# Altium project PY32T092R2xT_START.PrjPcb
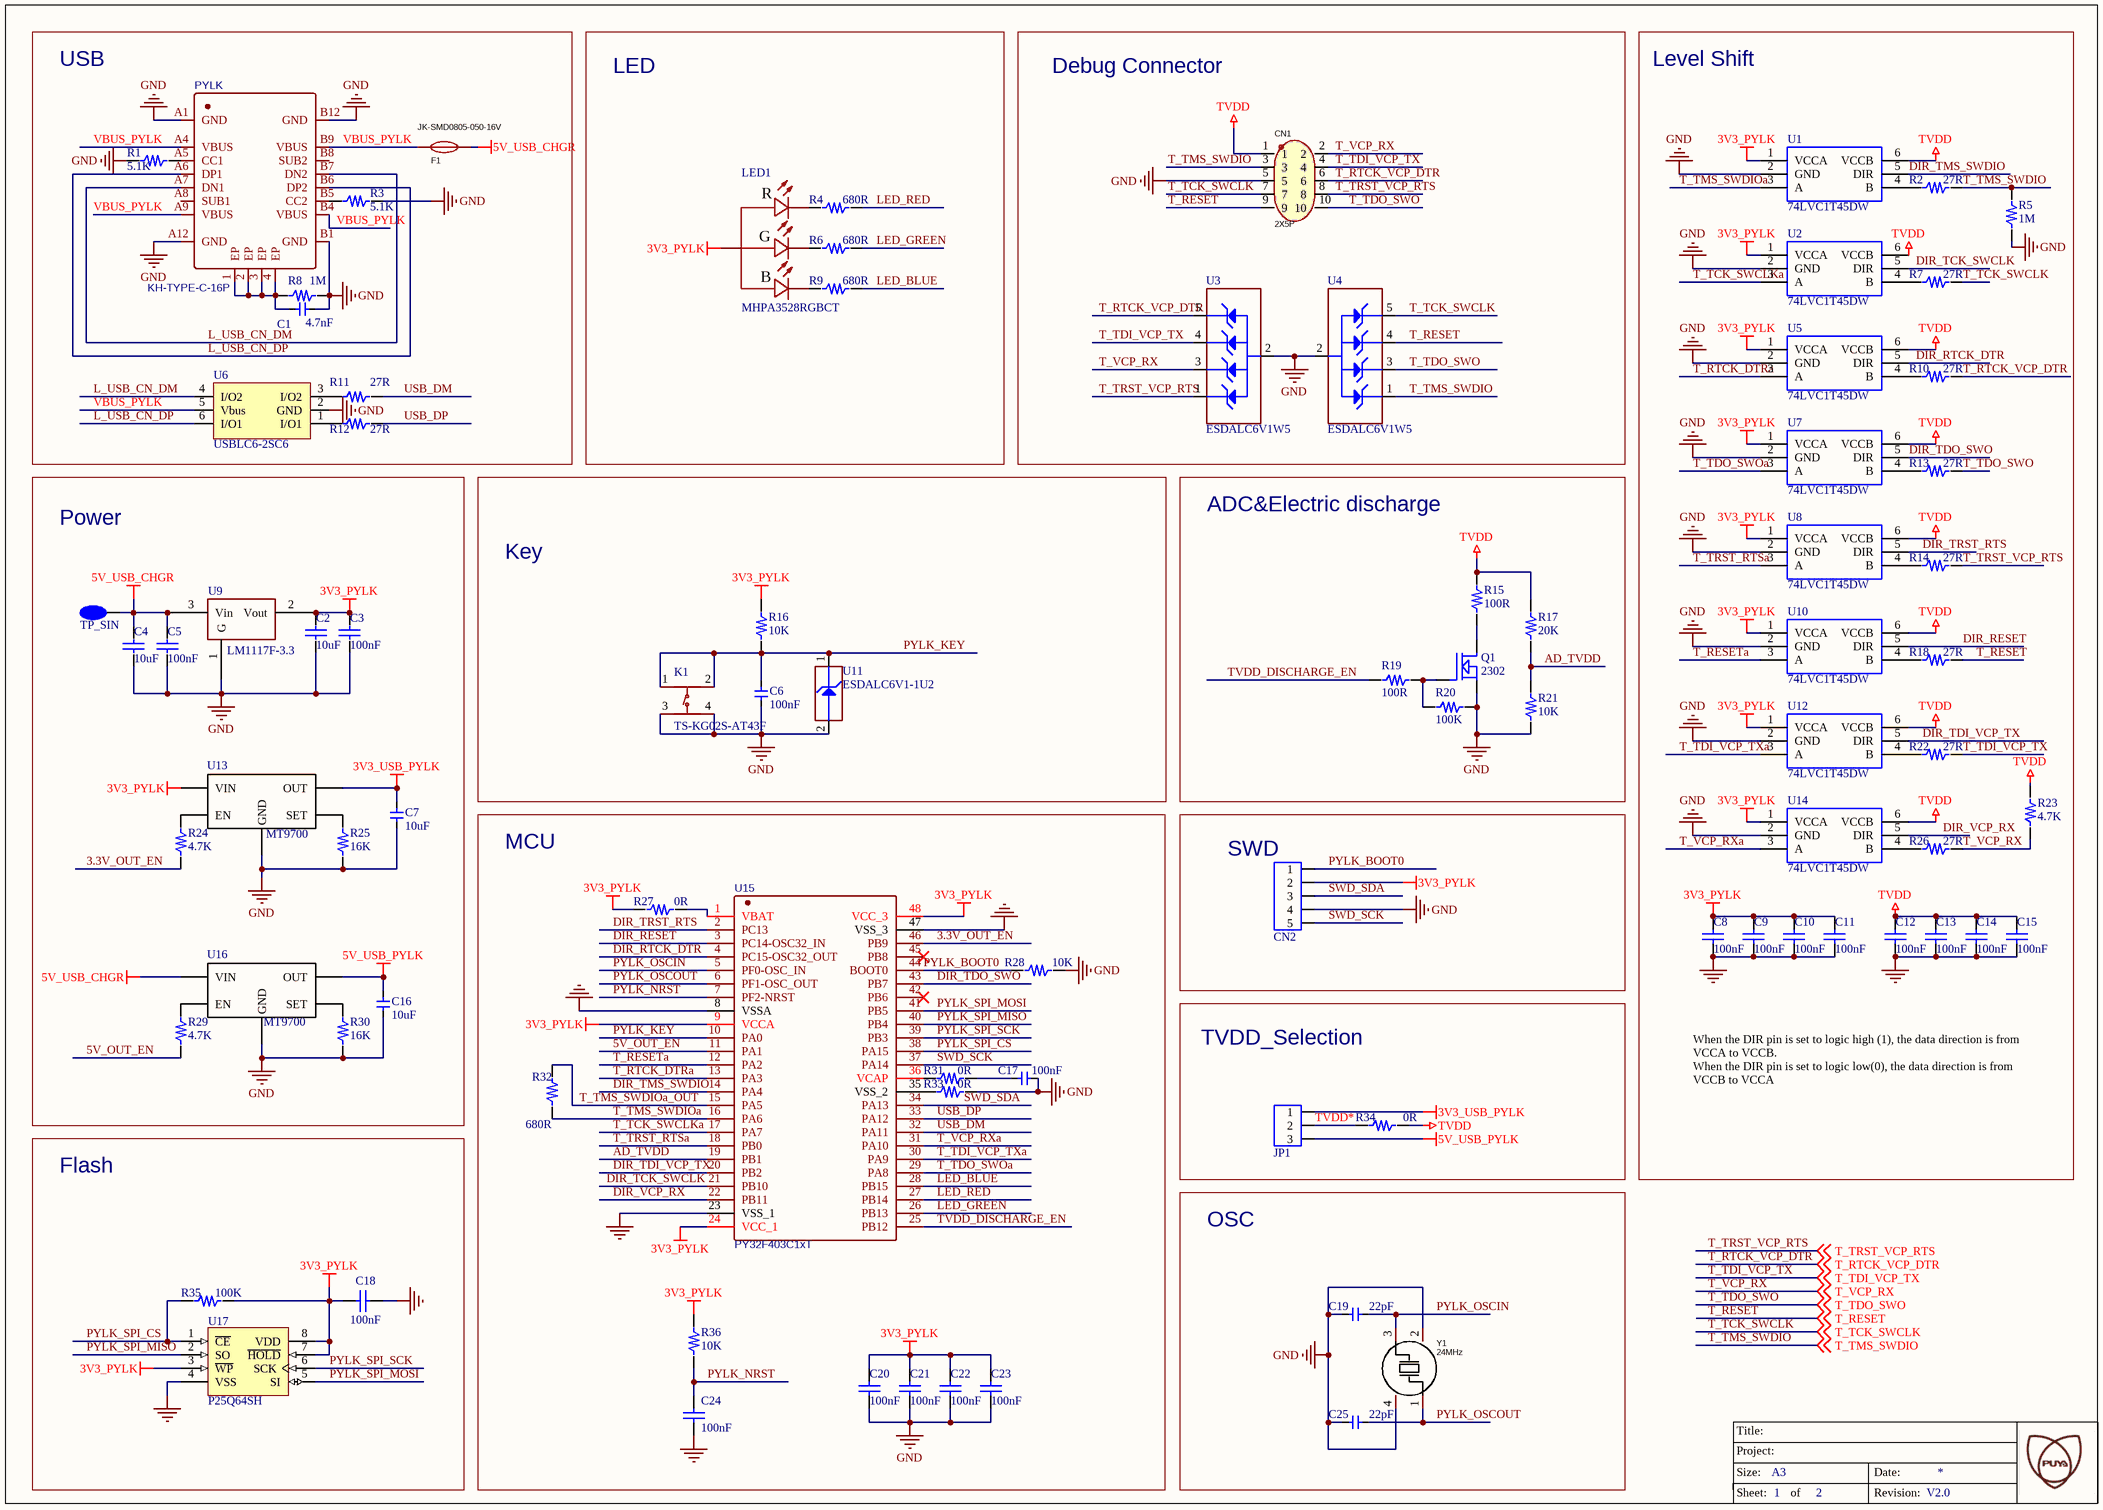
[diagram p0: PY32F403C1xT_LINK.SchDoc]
2 sheets, 144 parts. Net scope: global (net labels, ports and power ports of the same name join across sheets).
Board file: PY32T092R2xT_START.PcbDoc
Sheets:
  PY32F403C1xT_LINK.SchDoc
  PY32T092R2xT_START.SchDoc

## Sheet PY32F403C1xT_LINK.SchDoc: =DocumentName
size A3; Revision: V2.0; SheetNumber: 1; SheetTotal: 2; Project: PY32T092R2xT_START.PrjPcb

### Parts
5V_USB_CHGR  TP_SIN  [TP_SIN]
C1  4.7nF  [C0603]
C2  10uF  [C0805]
C3  100nF  [C0603]
C4  10uF  [C0805]
C5  100nF  [C0603]
C6  100nF  [C0603]
C7  10uF  [C0805]
C8  100nF  [C0603]
C9  100nF  [C0603]
C10  100nF  [C0603]
C11  100nF  [C0603]
C12  100nF  [C0603]
C13  100nF  [C0603]
C14  100nF  [C0603]
C15  100nF  [C0603]
C16  10uF  [C0805]
C17  100nF  [C0603]
C18  100nF  [C0603]
C19  22pF  [C0603]
C20  100nF  [C0603]
C21  100nF  [C0603]
C22  100nF  [C0603]
C23  100nF  [C0603]
C24  100nF  [C0603]
C25  22pF  [C0603]
CN1  2X5P  [HDR2X5]
CN2  CON5  [CON5]  (value not drawn)
F1  JK-SMD0805-050-16V  [F0805]
JP1  CON3  [CON3]  (value not drawn)
K1  TS-KG02S-AT43F  [SW-SMD_4P-L6.0-W6.0-P4.50-LS8.5]
LED1  MHPA3528RGBCT  [LED-ARRAY-SMD_4P-L3.5-W2.8-TL]
PYLK  KH-TYPE-C-16P  [USB-C-SMD_KH-TYPE-C-16P]
Q1  2302  [SOT23]
R1  5.1K  [R0603]
R2  27R  [R0603]
R3  5.1K  [R0603]
R4  680R  [R0603]
R5  1M  [R0603]
R6  680R  [R0603]
R7  27R  [R0603]
R8  1M  [R0603]
R9  680R  [R0603]
R10  27R  [R0603]
R11  27R  [R0603]
R12  27R  [R0603]
R13  27R  [R0603]
R14  27R  [R0603]
R15  100R  [R0805]
R16  10K  [R0603]
R17  20K  [R0603]
R18  27R  [R0603]
R19  100R  [R0603]
R20  100K  [R0603]
R21  10K  [R0603]
R22  27R  [R0603]
R23  4.7K  [R0603]
R24  4.7K  [R0603]
R25  16K  [R0603]
R26  27R  [R0603]
R27  0R  [JP2_SMD]
R28  10K  [R0603]
R29  4.7K  [R0603]
R30  16K  [R0603]
R31  0R  [JP2_SMD]
R32  680R  [R0603]
R33  0R  [JP2_SMD]
R34  0R  [JP2_SMD]
R35  100K  [R0603]
R36  10K  [R0603]
U1  74LVC1T45DW  [SOT363]
U2  74LVC1T45DW  [SOT363]
U3  ESDALC6V1W5  [ESD_SOT323-5L]
U4  ESDALC6V1W5  [ESD_SOT323-5L]
U5  74LVC1T45DW  [SOT363]
U6  USBLC6-2SC6  [SOT23-6]
U7  74LVC1T45DW  [SOT363]
U8  74LVC1T45DW  [SOT363]
U9  LM1117F-3.3  [SOT-89-3_L4.5-W2.5-P1.50-LS4.2-BR]
U10  74LVC1T45DW  [SOT363]
U11  ESDALC6V1-1U2  [ESD_ST0201]
U12  74LVC1T45DW  [SOT363]
U13  MT9700  [SOT23-5]
U14  74LVC1T45DW  [SOT363]
U15  PY32F403C1xT  [LQFP-48_L7.0-W7.0-P0.50-LS9.0-BL]
U16  MT9700  [SOT23-5]
U17  P25Q64SH  [SOP-8P]
Y1  24MHz  [CRYSTAL-SMD_4P-L3.2-W2.5-BL]

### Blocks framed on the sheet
USB: C1 F1 PYLK R1 R3 R8 R11 R12 U6
LED: LED1 R4 R6 R9
Debug Connector: CN1 U3 U4
Level Shift: C8-C15 R2 R5 R7 R10 R13 R14 R18 R22 R23 R26 U1 U2 U5 U7 U8 U10 U12 U14
Power: 5V_USB_CHGR C2-C5 C7 C16 R24 R25 R29 R30 U9 U13 U16
Key: C6 K1 R16 U11
ADC&Electric discharge: Q1 R15 R17 R19-R21
MCU: C17 C20-C24 R27 R28 R31-R33 R36 U15
SWD: CN2
TVDD_Selection: JP1 R34
Flash: C18 R35 U17
OSC: C19 C25 Y1

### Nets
3V3_PYLK: C2.2 C3.2 C8.2 C9.2 C10.2 C11.2 C18.2 C20.2 C21.2 C22.2 C23.2 CN2.2 LED1.1(-) R16.2 R27.1 R35.2 R36.2 U1.1(VCCA) U2.1(VCCA) U5.1(VCCA) U7.1(VCCA) U8.1(VCCA) U9.2(Vout) U10.1(VCCA) U12.1(VCCA) U13.5(VIN) U14.1(VCCA) U15.9(VCCA) U15.24(VCC_1) U15.48(VCC_3) U17.3(~{WP}) U17.7(~{HOLD}) U17.8(VDD)
3V3_USB_PYLK: C7.2 JP1.1 U13.1(OUT)
5V_USB_CHGR: 5V_USB_CHGR.1(TP_SIN) C4.2 C5.2 F1.2 U9.3(Vin) U16.5(VIN)
5V_USB_PYLK: C16.2 JP1.3 U16.1(OUT)
GND: C1.1 C2.1 C3.1 C4.1 C5.1 C6.1 C7.1 C8.1 C9.1 C10.1 C11.1 C12.1 C13.1 C14.1 C15.1 C16.1 C17.1 C18.1 C19.1 C20.1 C21.1 C22.1 C23.1 C24.1 C25.1 CN1.5 CN2.4 K1.3 K1.4 PYLK.A1(GND) PYLK.A12(GND) PYLK.B1(GND) PYLK.B12(GND) Q1.2(S) R1.1 R3.2 R5.1 R8.2 R20.1 R21.1 R25.1 R28.2 R30.1 R33.2 U1.2(GND) U2.2(GND) U3.2(GND) U4.2(GND) U5.2(GND) U6.2(GND) U7.2(GND) U8.2(GND) U9.1(G) U10.2(GND) U11.2(GND) U12.2(GND) U13.2(GND) U14.2(GND) U15.8(VSSA) U15.23(VSS_1) U15.47(VSS_3) U16.2(GND) U17.4(VSS) Y1.2(GND) Y1.4(GND)
TVDD: C12.2 C13.2 C14.2 C15.2 CN1.1 R15.2 R17.2 R23.2 R34.2 U1.6(VCCB) U2.6(VCCB) U5.6(VCCB) U7.6(VCCB) U8.6(VCCB) U10.6(VCCB) U12.6(VCCB) U14.6(VCCB)
3.3V_OUT_EN: R24.1 U15.46(PB9)
5V_OUT_EN: R29.1 U15.11(PA1)
AD_TVDD: R17.1 R21.2 U15.19(PB1)
DIR_RESET: U10.5(DIR) U15.3(PC14-OSC32_IN)
DIR_RTCK_DTR: U5.5(DIR) U15.4(PC15-OSC32_OUT)
DIR_TCK_SWCLK: U2.5(DIR) U15.21(PB10)
DIR_TDI_VCP_TX: U12.5(DIR) U15.20(PB2)
DIR_TDO_SWO: U7.5(DIR) U15.43(PB7)
DIR_TMS_SWDIO: U1.5(DIR) U15.14(PA4)
DIR_TRST_RTS: U8.5(DIR) U15.2(PC13)
DIR_VCP_RX: U14.5(DIR) U15.22(PB11)
L_USB_CN_DM: PYLK.A7(DN1) PYLK.B7(DN2) U6.4(I/O2)
L_USB_CN_DP: PYLK.A6(DP1) PYLK.B6(DP2) U6.6(I/O1)
LED_BLUE: R9.2 U15.28(PB15)
LED_GREEN: R6.2 U15.26(PB13)
LED_RED: R4.2 U15.27(PB14)
PYLK_BOOT0: CN2.1 R28.1 U15.44(BOOT0)
PYLK_KEY: C6.2 K1.1 K1.2 R16.1 U11.1(IO1) U15.10(PA0)
PYLK_NRST: C24.2 R36.1 U15.7(PF2-NRST)
PYLK_OSCIN: C19.2 U15.5(PF0-OSC_IN) Y1.3(OSC2)
PYLK_OSCOUT: C25.2 U15.6(PF1-OSC_OUT) Y1.1(OSC1)
PYLK_SPI_CS: R35.1 U15.38(PA15) U17.1(~{CE})
PYLK_SPI_MISO: U15.40(PB4) U17.2(SO)
PYLK_SPI_MOSI: U15.41(PB5) U17.5(SI)
PYLK_SPI_SCK: U15.39(PB3) U17.6(SCK)
SWD_SCK: CN2.5 U15.37(PA14)
SWD_SDA: CN2.3 U15.34(PA13)
T_RESET: CN1.9 R18.2 U4.4(IO3) ; off-sheet T_RESET
T_RESETa: U10.3(A) U15.12(PA2)
T_RTCK_DTRa: U5.3(A) U15.13(PA3)
T_RTCK_VCP_DTR: CN1.6 R10.2 U3.5(IO4) ; off-sheet T_RTCK_VCP_DTR
T_TCK_SWCLK: CN1.7 R7.2 U4.5(IO4) ; off-sheet T_TCK_SWCLK
T_TCK_SWCLKa: U2.3(A) U15.17(PA7)
T_TDI_VCP_TX: CN1.4 R22.2 U3.4(IO3) ; off-sheet T_TDI_VCP_TX
T_TDI_VCP_TXa: U12.3(A) U15.30(PA9)
T_TDO_SWO: CN1.10 R13.2 U4.3(IO2) ; off-sheet T_TDO_SWO
T_TDO_SWOa: U7.3(A) U15.29(PA8)
T_TMS_SWDIO: CN1.3 R2.2 R5.2 U4.1(IO1) ; off-sheet T_TMS_SWDIO
T_TMS_SWDIOa: R32.1 U1.3(A) U15.16(PA6)
T_TMS_SWDIOa_OUT: R32.2 U15.15(PA5)
T_TRST_RTSa: U8.3(A) U15.18(PB0)
T_TRST_VCP_RTS: CN1.8 R14.2 U3.1(IO1) ; off-sheet T_TRST_VCP_RTS
T_VCP_RX: CN1.2 R23.1 R26.2 U3.3(IO2) ; off-sheet T_VCP_RX
T_VCP_RXa: U14.3(A) U15.31(PA10)
TVDD*: JP1.2 R34.1
TVDD_DISCHARGE_EN: R19.2 U15.25(PB12)
USB_DM: R11.2 U15.32(PA11)
USB_DP: R12.2 U15.33(PA12)
VBUS_PYLK: F1.1 PYLK.A4(VBUS) PYLK.A9(VBUS) PYLK.B4(VBUS) PYLK.B9(VBUS) U6.5(Vbus)
NetC1_2: C1.2 PYLK.1(EP) PYLK.2(EP) PYLK.3(EP) PYLK.4(EP) R8.1
NetC17_2: C17.2 R31.2
NetLED1_2: LED1.2(-) R9.1
NetLED1_3: LED1.3(-) R6.1
NetLED1_4: LED1.4(-) R4.1
NetPYLK_A5: PYLK.A5(CC1) R1.2
NetPYLK_B5: PYLK.B5(CC2) R3.1
NetQ1_1: Q1.1(G) R19.1 R20.2
NetQ1_3: Q1.3(D) R15.1
NetR2_1: R2.1 U1.4(B)
NetR7_1: R7.1 U2.4(B)
NetR10_1: R10.1 U5.4(B)
NetR11_1: R11.1 U6.3(I/O2)
NetR12_1: R12.1 U6.1(I/O1)
NetR13_1: R13.1 U7.4(B)
NetR14_1: R14.1 U8.4(B)
NetR18_1: R18.1 U10.4(B)
NetR22_1: R22.1 U12.4(B)
NetR24_2: R24.2 U13.4(EN)
NetR25_2: R25.2 U13.3(SET)
NetR26_1: R26.1 U14.4(B)
NetR27_2: R27.2 U15.1(VBAT)
NetR29_2: R29.2 U16.4(EN)
NetR30_2: R30.2 U16.3(SET)
NetR31_1: R31.1 U15.36(VCAP)
NetR33_1: R33.1 U15.35(VSS_2)

Not connected (* = marked no-connect by the designer): PYLK A8(SUB1) B8(SUB2); U15 42(PB6)* 45(PB8)*

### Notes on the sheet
- When the DIR pin is set to logic high (1), the data direction is from VCCA to VCCB.
  When the DIR pin is set to logic low(0), the data direction is from VCCB to VCCA

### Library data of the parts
C1 C3 C5 C6 C17 C19 C25 = C0603: PCB DECAL: 0603
C2 C4 C7 C16 = C0805: PCB DECAL: 0805
C8-C15 C18 C20-C24 = 贴片高压陶瓷电容: Capacitor (Semiconductor SIM Model); 器件封装(外观): 0603; Value: 104
CN1 = 2X5P: Manufacturer: XFCN(兴飞); Symbol: PZ254V-12-10P; Add into BOM: yes; Pitch: 2.54mm; Circluar Pins/Square Pins: 方针
F1 = JK-SMD0805-050-16V: Manufacturer: JK(金科); Add into BOM: yes; Voltage - Max: 6V; Current - Max: 100A; Hold Current: 500mA; Trip Current: 1A; Power Dissipation: 600mW; Resistance - Initial (Ri) (Min): 150mΩ; Resistance - Post Trip (R1) (Max): 850mΩ; Time to Trip(Max): 100ms
K1 = TS-KG02S-AT43F: Manufacturer: HANBO(汉博); Add into BOM: yes; Circuit: 单刀单掷; Actuator Style: 圆形按钮; Operating Force: 250gf; Switch Length: 6mm; Switch Height: 4.3mm; Strike Gundam: 不带; Contact Current: 50mA; Voltage Rating (DC): 12V; Insulation Resistance: 100MΩ; Actuator/Cap Color: 黑色; Pin Style: 鸥翼型
LED1 = MHPA3528RGBCT: Manufacturer: MEIHUA(美华); Add into BOM: yes
PYLK = KH-TYPE-C-16P: BOM_Manufacturer: Shenzhen Kinghelm Elec; Contributor: LCSC
Q1 = MOSFET N: Value: SI2302
R1-R14 R16-R24 R26-R29 R31-R36 = R0603: PCB DECAL: 0603
R15 = R0805: PCB DECAL: 0805
R25 R30 = R0603_7: 0603WAF1602T5E 16KΩ(1602) ±1%; PCB DECAL: 0603
U3 U4 = ESDALC6V1W5: Dual Transil array for ESD protection; Internal_Part_Number: MCD-00136; Part_Type: Diode; Manufacturer: STMICROELECTRONICS; ECCN_US: EAR99; ECCN_EU: NEC; Provided_By: Subcon; Initial_Board_Reference: MB1262
U6 = USBLC6-2SC6: Function: ESD EMI fliter
U11 = ESDALC6V1-1U2: ESD protection 6V1; Internal_Part_Number: MCD-00170; Part_Type: Diode; Manufacturer: STMICROELECTRONICS; ECCN_US: EAR99; ECCN_EU: NEC; Provided_By: Subcon; Initial_Board_Reference: MB1274
U15 = PY32F403C1xT: LQFP48; BOM_Manufacturer: PUYA(普冉)
U17 = SST25VF010: Value: SST25VF020B; 器件封装(外观): SOP8
Y1 = ABM8AIG-24.000MHZ-82Z-T: ±20ppm , 12.5pF , T_use: -40°C~125°C; Manufacturer: ABRACON; Add into BOM: yes; External load capacitor: 8pF; Frequency Stability(Full temperature range): ±50ppm; Equivalent Series Resistance (ESR): 50Ω

## Sheet PY32T092R2xT_START.SchDoc: =DocumentName
size A3; Revision: V2.0; SheetNumber: 2; SheetTotal: 2; Project: PY32T092R2xT_START.PrjPcb
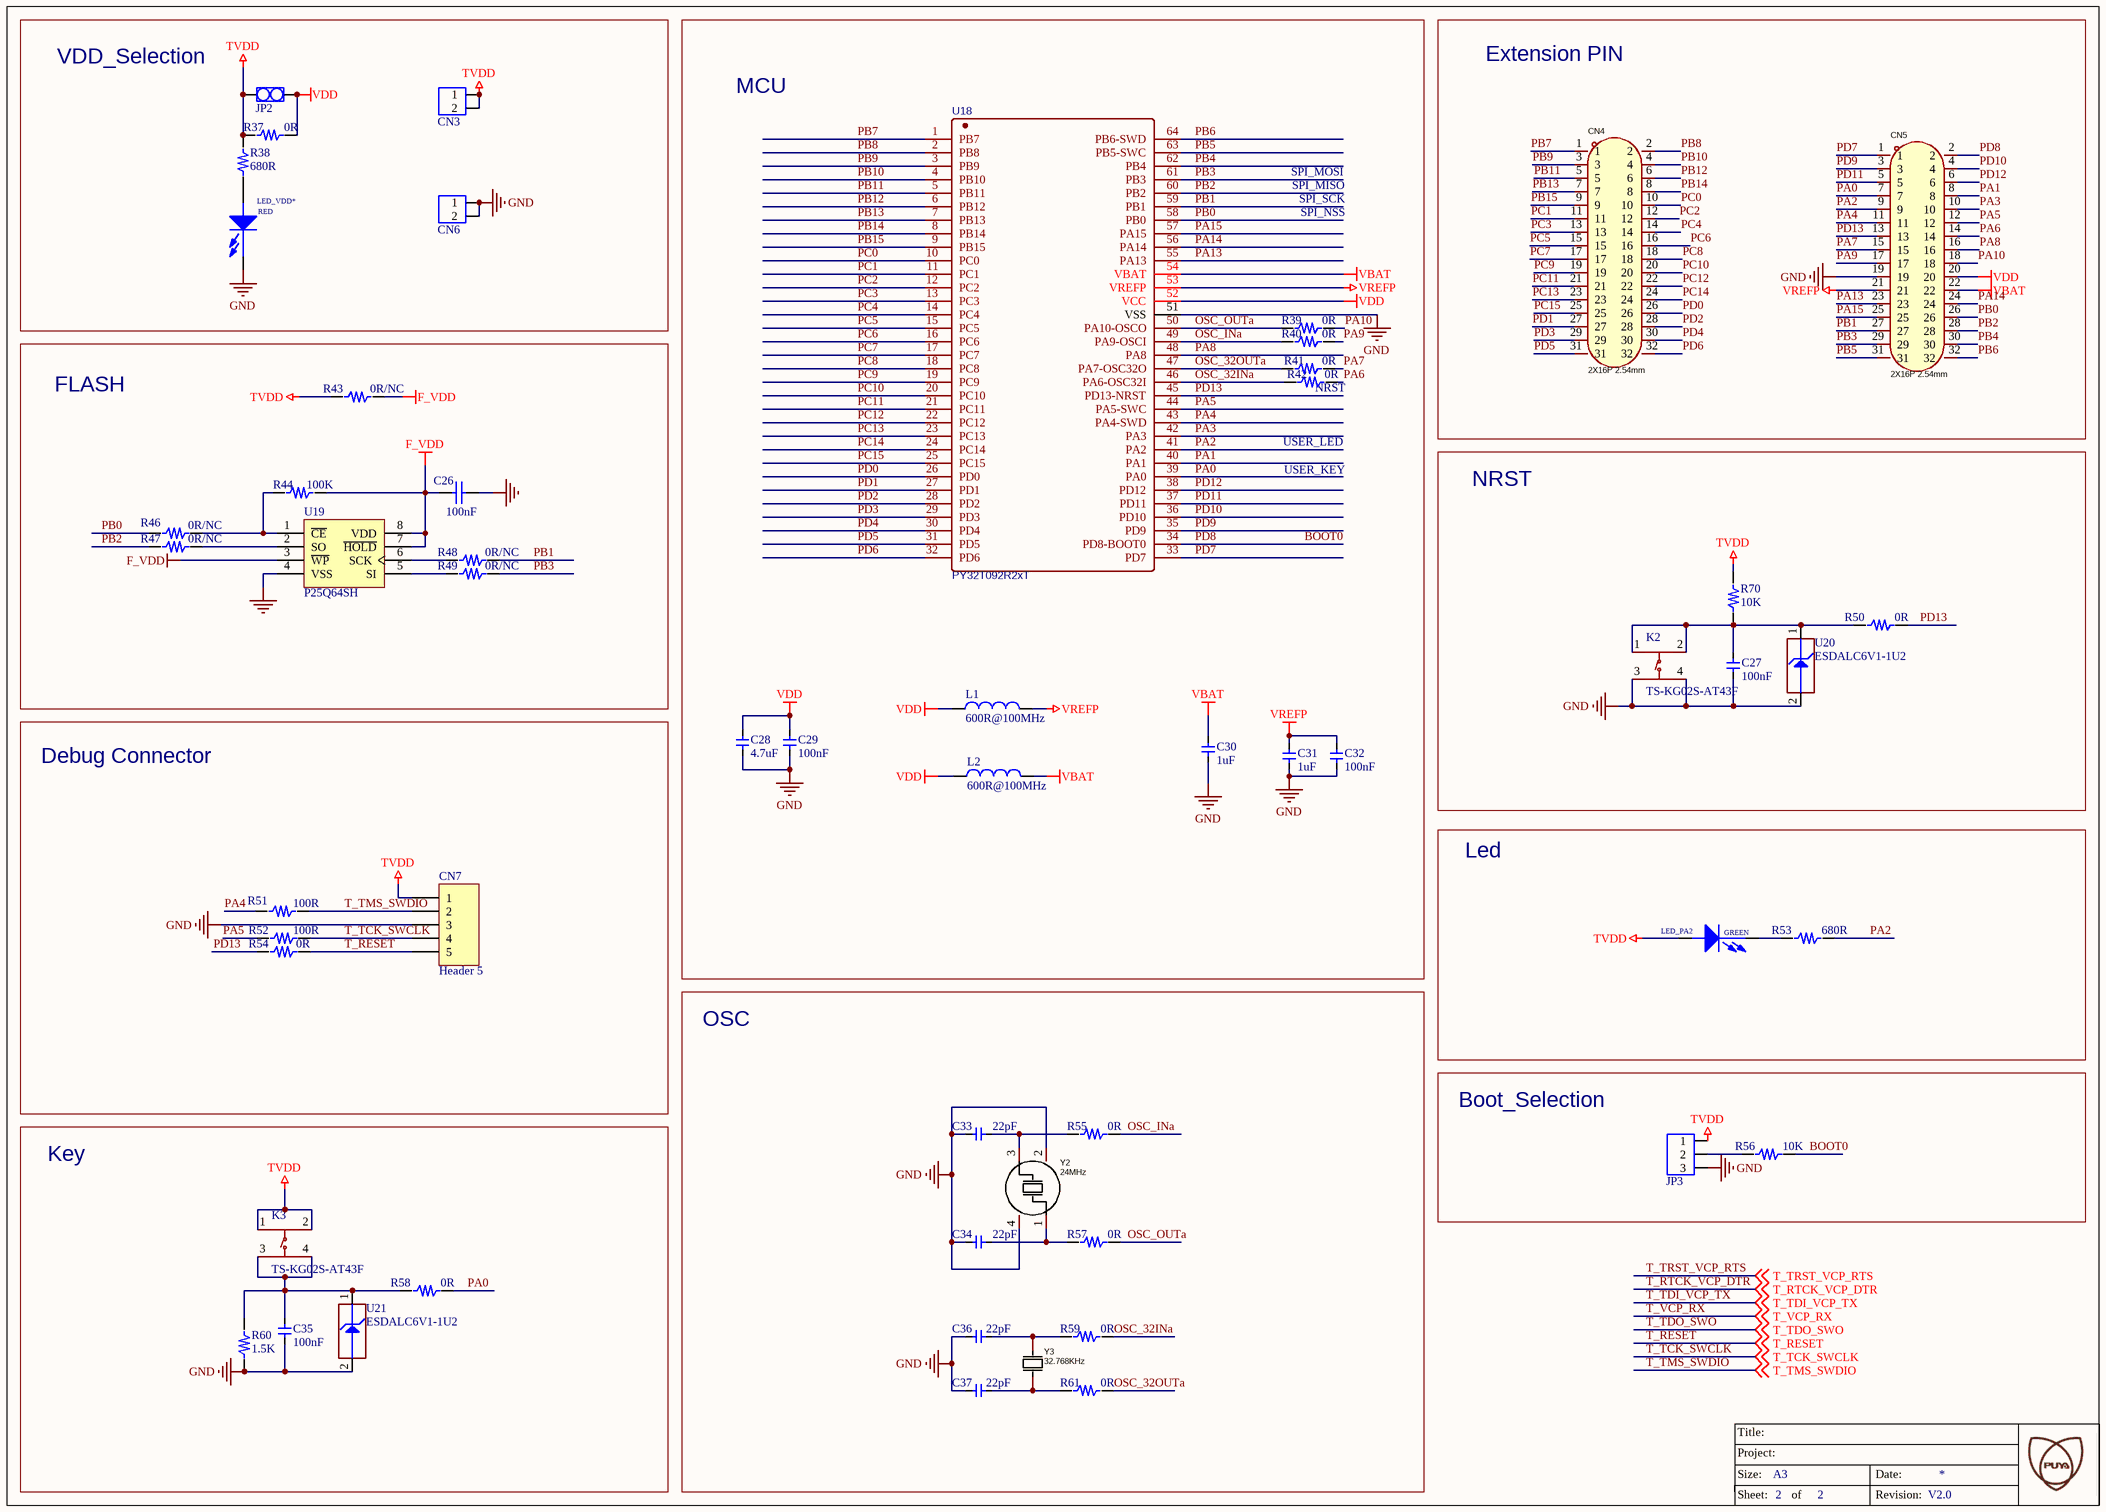
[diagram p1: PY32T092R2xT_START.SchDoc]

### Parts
C26  100nF  [C0603]
C27  100nF  [C0603]
C28  4.7uF  [C0603]
C29  100nF  [C0603]
C30  1uF  [C0603]
C31  1uF  [C0603]
C32  100nF  [C0603]
C33  22pF  [C0603]
C34  22pF  [C0603]
C35  100nF  [C0603]
C36  22pF  [C0603]
C37  22pF  [C0603]
CN3  CON2  [CON2]  (value not drawn)
CN4  2X16P 2.54mm  [HDR-TH_32P-P2.54-V-M-R2-C16-S2.54-3]
CN5  2X16P 2.54mm  [HDR-TH_32P-P2.54-V-M-R2-C16-S2.54-3]
CN6  CON2  [CON2]  (value not drawn)
CN7  Header 5  [HDR1X5]
JP2  CON2/NC  [CON2]  (value not drawn)
JP3  CON3  [CON3]  (value not drawn)
K2  TS-KG02S-AT43F  [SW-SMD_4P-L6.0-W6.0-P4.50-LS8.5]
K3  TS-KG02S-AT43F  [SW-SMD_4P-L6.0-W6.0-P4.50-LS8.5]
L1  value 600R@100MHz  [L0603]  (hidden comment: BEAD)
L2  value 600R@100MHz  [L0603]  (hidden comment: BEAD)
LED_PA2  GREEN  [0603_LED]
LED_VDD*  RED  [0603_LED]
R37  0R  [JP2_SMD]
R38  680R  [R0603]
R39  0R  [JP2_SMD]
R40  0R  [JP2_SMD]
R41  0R  [JP2_SMD]
R42  0R  [JP2_SMD]
R43  0R/NC  [JP2_SMD]
R44  100K  [R0603]
R46  0R/NC  [JP2_SMD]
R47  0R/NC  [JP2_SMD]
R48  0R/NC  [JP2_SMD]
R49  0R/NC  [JP2_SMD]
R50  0R  [JP2_SMD]
R51  100R  [JP2_SMD]
R52  100R  [JP2_SMD]
R53  680R  [R0603]
R54  0R  [JP2_SMD]
R55  0R  [JP2_SMD]
R56  10K  [R0603]
R57  0R  [JP2_SMD]
R58  0R  [JP2_SMD]
R59  0R  [JP2_SMD]
R60  1.5K  [R0603]
R61  0R  [JP2_SMD]
R70  10K  [R0603]
U18  PY32T092R2xT  [LQFP-64_L10.0-W10.0-P0.50-LS12.0-BL]
U19  P25Q64SH  [SOP-8P]
U20  ESDALC6V1-1U2  [ESD_ST0201]
U21  ESDALC6V1-1U2  [ESD_ST0201]
Y2  24MHz  [CRYSTAL-SMD_4P-L3.2-W2.5-BL]
Y3  32.768KHz  [CRYSTAL-SMD_L3.2-W1.5-1]

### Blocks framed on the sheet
VDD_Selection: CN3 CN6 JP2 LED_VDD* R37 R38
MCU: C28-C32 L1 L2 R39-R42 U18
Extension PIN: CN4 CN5
FLASH: C26 R43 R44 R46-R49 U19
NRST: C27 K2 R50 R70 U20
Debug Connector: CN7 R51 R52 R54
Led: LED_PA2 R53
OSC: C33 C34 C36 C37 R55 R57 R59 R61 Y2 Y3
Boot_Selection: JP3 R56
Key: C35 K3 R58 R60 U21

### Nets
F_VDD: C26.2 R43.1 R44.2 U19.3(~{WP}) U19.7(~{HOLD}) U19.8(VDD)
GND: C26.1 C27.1 C28.2 C29.2 C30.2 C31.2 C32.2 C33.1 C34.1 C35.1 C36.1 C37.1 CN5.19 CN6.1 CN6.2 CN7.3 JP3.3 K2.3 K2.4 LED_VDD*.2(CATHODE) R60.1 U18.51(VSS) U19.4(VSS) U20.2(GND) U21.2(GND) Y2.2(GND) Y2.4(GND)
TVDD: CN3.1 CN3.2 CN7.1 JP2.1 JP3.1 K3.1 K3.2 LED_PA2.1(ANODE) R37.1 R38.2 R43.2 R70.1
VBAT: C30.1 CN5.22 L2.2 U18.54(VBAT)
VDD: C28.1 C29.1 CN5.20 JP2.2 L1.1 L2.1 R37.2 U18.52(VCC)
VREFP: C31.1 C32.1 CN5.21 L1.2 U18.53(VREFP)
BOOT0: CN5.2 R56.2 U18.34(PD8-BOOT0)  [also labelled PD8]
OSC_32INa: R42.1 R59.2 U18.46(PA6-OSC32I)
OSC_32OUTa: R41.1 R61.2 U18.47(PA7-OSC32O)
OSC_INa: R40.1 R55.2 U18.49(PA9-OSCI)
OSC_OUTa: R39.1 R57.2 U18.50(PA10-OSCO)
PA0: CN5.7 R58.2 U18.39(PA0)
PA1: CN5.8 U18.40(PA1)
PA2: CN5.9 R53.2 U18.41(PA2)
PA3: CN5.10 U18.42(PA3)
PA4: CN5.11 R51.2 U18.43(PA4-SWD)
PA5: CN5.12 R52.2 U18.44(PA5-SWC)
PA6: CN5.14 R42.2
PA7: CN5.15 R41.2
PA8: CN5.16 U18.48(PA8)
PA9: CN5.17 R40.2
PA10: CN5.18 R39.2
PA13: CN5.23 U18.55(PA13)
PA14: CN5.24 U18.56(PA14)
PA15: CN5.25 U18.57(PA15)
PB0: CN5.26 R46.2 U18.58(PB0)
PB1: CN5.27 R48.1 U18.59(PB1)
PB2: CN5.28 R47.2 U18.60(PB2)
PB3: CN5.29 R49.1 U18.61(PB3)
PB4: CN5.30 U18.62(PB4)
PB5: CN5.31 U18.63(PB5-SWC)
PB6: CN5.32 U18.64(PB6-SWD)
PB7: CN4.1 U18.1(PB7)
PB8: CN4.2 U18.2(PB8)
PB9: CN4.3 U18.3(PB9)
PB10: CN4.4 U18.4(PB10)
PB11: CN4.5 U18.5(PB11)
PB12: CN4.6 U18.6(PB12)
PB13: CN4.7 U18.7(PB13)
PB14: CN4.8 U18.8(PB14)
PB15: CN4.9 U18.9(PB15)
PC0: CN4.10 U18.10(PC0)
PC1: CN4.11 U18.11(PC1)
PC2: CN4.12 U18.12(PC2)
PC3: CN4.13 U18.13(PC3)
PC4: CN4.14 U18.14(PC4)
PC5: CN4.15 U18.15(PC5)
PC6: CN4.16 U18.16(PC6)
PC7: CN4.17 U18.17(PC7)
PC8: CN4.18 U18.18(PC8)
PC9: CN4.19 U18.19(PC9)
PC10: CN4.20 U18.20(PC10)
PC11: CN4.21 U18.21(PC11)
PC12: CN4.22 U18.22(PC12)
PC13: CN4.23 U18.23(PC13)
PC14: CN4.24 U18.24(PC14)
PC15: CN4.25 U18.25(PC15)
PD0: CN4.26 U18.26(PD0)
PD1: CN4.27 U18.27(PD1)
PD2: CN4.28 U18.28(PD2)
PD3: CN4.29 U18.29(PD3)
PD4: CN4.30 U18.30(PD4)
PD5: CN4.31 U18.31(PD5)
PD6: CN4.32 U18.32(PD6)
PD7: CN5.1 U18.33(PD7)
PD9: CN5.3 U18.35(PD9)
PD10: CN5.4 U18.36(PD10)
PD11: CN5.5 U18.37(PD11)
PD12: CN5.6 U18.38(PD12)
PD13: CN5.13 R50.2 R54.2 U18.45(PD13-NRST)
T_RESET: CN7.5 R54.1 ; off-sheet T_RESET
T_TCK_SWCLK: CN7.4 R52.1 ; off-sheet T_TCK_SWCLK
T_TMS_SWDIO: CN7.2 R51.1 ; off-sheet T_TMS_SWDIO
NetC27_2: C27.2 K2.1 K2.2 R50.1 R70.2 U20.1(IO1)
NetC33_2: C33.2 R55.1 Y2.3(OSC2)
NetC34_2: C34.2 R57.1 Y2.1(OSC1)
NetC35_2: C35.2 K3.3 K3.4 R58.1 R60.2 U21.1(IO1)
NetC36_2: C36.2 R59.1 Y3.2(OSC2)
NetC37_2: C37.2 R61.1 Y3.1(OSC1)
NetJP3_2: JP3.2 R56.1
NetLED_PA2_2: LED_PA2.2(CATHODE) R53.1
NetLED_VDD*_1: LED_VDD*.1(ANODE) R38.1
NetR44_1: R44.1 R46.1 U19.1(~{CE})
NetR47_1: R47.1 U19.2(SO)
NetR48_2: R48.2 U19.6(SCK)
NetR49_2: R49.2 U19.5(SI)

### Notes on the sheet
- SPI_MOSI
- SPI_MISO
- SPI_SCK
- SPI_NSS
- USER_LED
- (near R42) NRST
- USER_KEY

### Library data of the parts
C26 = 贴片高压陶瓷电容: as C8 on sheet PY32F403C1xT_LINK
C27-C37 = C0603: PCB DECAL: 0603
CN4 CN5 = 2X16P 2.54mm: Manufacturer: XKB Connection(中国星坤); Symbol: X6522WV-2X16H-C60D30-E80; Add into BOM: yes; Circluar Pins/Square Pins: 方针; Current Rating (Max): 3A; Voltage Rating (Max): 250V; Soldering Temperature(Max): 260℃
CN7 = Header 5: Header, 5-Pin
JP2 = CON2_DIP
K2 K3 = TS-KG02S-AT43F: as K1 on sheet PY32F403C1xT_LINK
L1 L2 = BEAD: SMD Chip ferrite bead, 600R@100MHz +/-25%, 350mA, 500mohm DC, 0603, T=0.8mm; Internal_Part_Number: MCD-00047; Part_Type: Inductor; Manufacturer_Part_Number: FCM1608KF-601T03; Manufacturer: TAI-TECH; Provided_By: SUBCO
LED_PA2 LED_VDD* = PDI-E803_Dup1
R37-R44 R46-R61 R70 = R0603: PCB DECAL: 0603
U18 = PY32L090R2xTx: LQFP64; BOM_Manufacturer: PUYA(普冉); BOM_Manufacturer Part: PY32CA00R1x
U19 = SST25VF010: Value: SST25VF020B; 器件封装(外观): SOP8
U20 U21 = ESDALC6V1-1U2: as U11 on sheet PY32F403C1xT_LINK
Y2 = ABM8AIG-24.000MHZ-82Z-T: as Y1 on sheet PY32F403C1xT_LINK
Y3 = XKXGI-SUA-32.768K: ±20ppm , 12.5pF , T_use: -40°C~125°C; Manufacturer: YXC(扬兴晶振); Add into BOM: yes; Crystal Type: 贴片晶振; Frequency Stability(Full temperature range): ±30ppm

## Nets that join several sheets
GND: PY32F403C1xT_LINK (65 pins), PY32T092R2xT_START (27 pins)
TVDD: PY32F403C1xT_LINK (17 pins), PY32T092R2xT_START (12 pins)
T_RESET: PY32F403C1xT_LINK (CN1.9 R18.2 U4.4), PY32T092R2xT_START (CN7.5 R54.1)
T_TCK_SWCLK: PY32F403C1xT_LINK (CN1.7 R7.2 U4.5), PY32T092R2xT_START (CN7.4 R52.1)
T_TMS_SWDIO: PY32F403C1xT_LINK (CN1.3 R2.2 R5.2 U4.1), PY32T092R2xT_START (CN7.2 R51.1)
